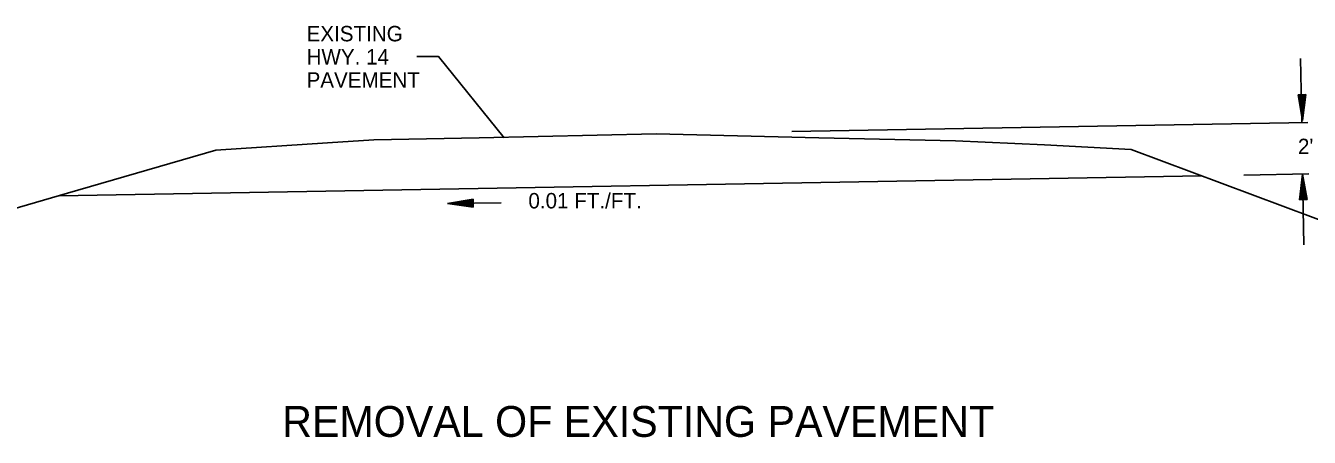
# Model space of a CAD drawing. Extents: x 635488 to 635865, y 290537 to 290973.
# Drawn here: x 635687.65 to 635737.65, y 290556.22 to 290572.23 of the extents above; entities that cross this region are included whole.
import ezdxf

# ---------------------------------------------------------------- set-up
doc = ezdxf.new("R2010")
doc.units = 0
for name, color, linetype in [('Default', 7, 'Continuous'), ('E_Existing ROW', 7, 'Continuous'), ('R_Exist Surface', 7, 'Continuous')]:
    doc.layers.add(name, color=color, linetype=linetype)

msp = doc.modelspace()

# ---------------------------------------------------------------- linework, layer by layer
at = {"layer": 'Default'}
for p, q in [((635737.31, 290570.955), (635737.353, 290568.461)), ((635737.51, 290569.55), (635737.211, 290569.542)), ((635737.211, 290569.542), (635737.386, 290568.548)), ((635737.234, 290569.544), (635737.382, 290568.715)), ((635737.26, 290569.544), (635737.377, 290568.887)), ((635737.286, 290569.545), (635737.373, 290569.054)), ((635737.312, 290569.545), (635737.369, 290569.223)), ((635737.337, 290569.545), (635737.365, 290569.389)), ((635737.384, 290569.549), (635737.365, 290569.389)), ((635737.409, 290569.547), (635737.369, 290569.223)), ((635737.436, 290569.55), (635737.373, 290569.054)), ((635737.462, 290569.55), (635737.377, 290568.887)), ((635737.487, 290569.551), (635737.382, 290568.715)), ((635737.51, 290569.55), (635737.386, 290568.548)), ((635717.489, 290568.114), (635737.593, 290568.465)), ((635688.957, 290565.616), (635733.451, 290566.392)), ((635735.104, 290566.421), (635737.628, 290566.465)), ((635737.263, 290565.459), (635737.386, 290566.461)), ((635737.286, 290565.458), (635737.391, 290566.294)), ((635737.562, 290565.466), (635737.386, 290566.461)), ((635737.388, 290566.461), (635737.436, 290563.712)), ((635737.538, 290565.465), (635737.391, 290566.294)), ((635737.311, 290565.458), (635737.396, 290566.122)), ((635737.337, 290565.459), (635737.4, 290565.955)), ((635737.364, 290565.462), (635737.404, 290565.786)), ((635737.513, 290565.464), (635737.396, 290566.122)), ((635737.487, 290565.464), (635737.4, 290565.955)), ((635737.461, 290565.463), (635737.404, 290565.786)), ((635705.083, 290565.477), (635704.088, 290565.309)), ((635706.18, 290565.346), (635704.088, 290565.309)), ((635705.089, 290565.178), (635704.088, 290565.309)), ((635705.085, 290565.453), (635704.254, 290565.313)), ((635705.089, 290565.2), (635704.254, 290565.313)), ((635705.085, 290565.427), (635704.427, 290565.316)), ((635705.089, 290565.226), (635704.427, 290565.316)), ((635705.085, 290565.402), (635704.593, 290565.319)), ((635705.089, 290565.252), (635704.593, 290565.319)), ((635705.085, 290565.376), (635704.762, 290565.321)), ((635705.087, 290565.278), (635704.762, 290565.321)), ((635705.086, 290565.35), (635704.929, 290565.324)), ((635705.088, 290565.303), (635704.929, 290565.324)), ((635705.089, 290565.178), (635705.083, 290565.477)), ((635737.263, 290565.459), (635737.562, 290565.466)), ((635737.388, 290565.46), (635737.408, 290565.619)), ((635737.436, 290565.463), (635737.408, 290565.619))]:
    msp.add_line(p, q, dxfattribs=at)
msp.add_lwpolyline([(635702.885, 290571.028), (635703.739, 290571.028), (635706.294, 290567.87)], dxfattribs=at)
at = {"layer": 'R_Exist Surface'}
msp.add_lwpolyline([(635664.967, 290562.485), (635680.761, 290563.236), (635689.283, 290565.711), (635695.06, 290567.394), (635699.411, 290567.675), (635701.21, 290567.786), (635705.316, 290567.869), (635712.205, 290568.022), (635718.547, 290567.865), (635723.872, 290567.754), (635727.342, 290567.593), (635730.707, 290567.417), (635742.533, 290563.003), (635745.912, 290561.776), (635752.446, 290561.69)], dxfattribs=at)

# ---------------------------------------------------------------- texts
at = {"layer": 'Default'}
for s, p in [('EXISTING', (635698.594, 290571.623)), ('HWY. 14', (635698.594, 290570.722)), ('PAVEMENT', (635698.594, 290569.821)), ("2' MIN.", (635737.208, 290567.235)), ('0.01 FT./FT.', (635707.235, 290565.123))]:
    msp.add_text(s, height=0.6, dxfattribs=at).set_placement(p)
at = {"layer": 'E_Existing ROW'}
msp.add_text('REMOVAL OF EXISTING PAVEMENT', height=1.2, dxfattribs=at).set_placement((635697.645, 290556.235))

doc.saveas('drawing.dxf')
